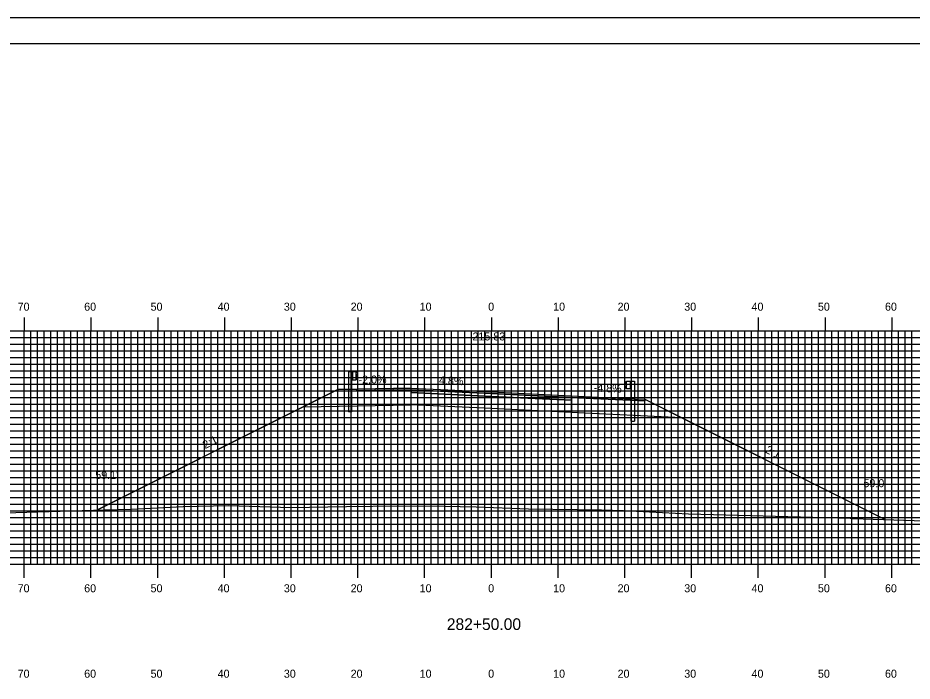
# Model space of a CAD drawing. Extents: x 1811374 to 1811717, y 442591 to 442811.
# Drawn here: x 1811468.4 to 1811602.4, y 442711.2 to 442810.5 of the extents above; entities that cross this region are included whole.
import ezdxf

# ---------------------------------------------------------------- set-up
doc = ezdxf.new("R2010")
doc.units = 0
for name, color, linetype in [('ANNOTATION', 7, 'Continuous'), ('BORDER', 7, 'Continuous'), ('D_Guardrail_Beam_Lt', 7, 'Continuous'), ('D_Guardrail_Beam_Rt', 7, 'Continuous'), ('D_Roadway_Centerline', 7, 'Continuous'), ('D_Roadway_Centerline_Text', 7, 'Continuous'), ('D_Roadway_Edge_Shoulder', 7, 'Continuous'), ('D_Roadway_Edge_TW', 7, 'Continuous'), ('D_Roadway_Pavement', 7, 'Continuous'), ('D_Roadway_SlopeLines', 7, 'Continuous'), ('D_Roadway_SubGrade', 7, 'Continuous'), ('D_Text_Standard', 7, 'Continuous'), ('H_V ANNOTATION', 7, 'Continuous'), ('MAJOR', 7, 'Continuous'), ('MINOR', 7, 'Continuous'), ('PLOT BOUNDARY', 7, 'Continuous'), ('S_Roadway_Centerline', 7, 'Continuous')]:
    doc.layers.add(name, color=color, linetype=linetype)

msp = doc.modelspace()

# ---------------------------------------------------------------- linework, layer by layer
at = {"layer": 'BORDER'}
msp.add_lwpolyline([(1811389.8, 442596.67), (1811709.8, 442596.67), (1811709.8, 442806.67), (1811389.8, 442806.67)], close=True, dxfattribs=at)
at = {"layer": 'D_Guardrail_Beam_Lt'}
for p, q in [((1811517.97, 442757.49), (1811517.97, 442751.49)), ((1811518.44, 442757.49), (1811517.97, 442757.49)), ((1811519.13, 442757.49), (1811518.44, 442757.49)), ((1811518.44, 442757.49), (1811518.44, 442756.33)), ((1811518.51, 442757.49), (1811518.51, 442756.33)), ((1811518.61, 442757.49), (1811518.61, 442756.33)), ((1811519.13, 442756.33), (1811519.13, 442757.49)), ((1811519.13, 442757.41), (1811519.21, 442757.39)), ((1811519.14, 442756.94), (1811519.14, 442756.87)), ((1811519.37, 442757.14), (1811519.17, 442757.01)), ((1811519.22, 442757.39), (1811519.37, 442757.29)), ((1811518.44, 442756.33), (1811519.13, 442756.33)), ((1811518.47, 442751.49), (1811518.47, 442756.33)), ((1811519.21, 442756.42), (1811519.13, 442756.41)), ((1811519.17, 442756.81), (1811519.37, 442756.67)), ((1811519.37, 442756.53), (1811519.22, 442756.43)), ((1811518.47, 442751.49), (1811517.97, 442751.49))]:
    msp.add_line(p, q, dxfattribs=at)
for centre, major_axis, start_param, end_param in [((1811519.22, 442756.94), (-0.0789, 0), 5.323254, 6.283185), ((1811519.22, 442756.87), (-0.0789, 0), 6.283185, 7.243116), ((1811519.2, 442757.35), (0.0417, 0), 0.959931, 1.376053), ((1811519.32, 442757.22), (0.0877, 0), 5.323254, 7.243116), ((1811519.2, 442756.46), (0.0417, 0), 4.907132, 5.323254), ((1811519.32, 442756.6), (0.0877, 0), 5.323254, 7.243116)]:
    msp.add_ellipse(centre, major_axis=major_axis, ratio=0.995501, start_param=start_param, end_param=end_param, dxfattribs=at)
at = {"layer": 'D_Guardrail_Beam_Rt'}
for p, q in [((1811559.58, 442756.01), (1811559.44, 442755.91)), ((1811559.44, 442755.77), (1811559.64, 442755.63)), ((1811559.67, 442756.03), (1811559.6, 442756.02)), ((1811559.67, 442756.12), (1811560.36, 442756.12)), ((1811559.67, 442754.95), (1811559.67, 442756.12)), ((1811559.67, 442755.57), (1811559.67, 442755.5)), ((1811560.19, 442756.12), (1811560.19, 442754.95)), ((1811560.3, 442756.12), (1811560.3, 442754.95)), ((1811560.36, 442756.12), (1811560.83, 442756.12)), ((1811560.36, 442756.12), (1811560.36, 442754.95)), ((1811560.83, 442756.12), (1811560.83, 442750.12)), ((1811559.64, 442755.43), (1811559.44, 442755.3)), ((1811559.44, 442755.15), (1811559.58, 442755.05)), ((1811559.6, 442755.05), (1811559.67, 442755.03)), ((1811560.36, 442754.95), (1811559.67, 442754.95)), ((1811560.34, 442750.12), (1811560.34, 442754.95)), ((1811560.34, 442750.12), (1811560.83, 442750.12))]:
    msp.add_line(p, q, dxfattribs=at)
for centre, major_axis, start_param, end_param in [((1811559.49, 442755.84), (-0.0877, 0), 5.323254, 7.243116), ((1811559.61, 442755.98), (-0.0417, 0), 4.907132, 5.323254), ((1811559.59, 442755.57), (0.0789, 0), 0, 0.959931), ((1811559.59, 442755.5), (0.0789, 0), 5.323254, 6.283185), ((1811559.49, 442755.23), (-0.0877, 0), 5.323254, 7.243116), ((1811559.61, 442755.09), (-0.0417, 0), 0.959931, 1.376053)]:
    msp.add_ellipse(centre, major_axis=major_axis, ratio=0.995501, start_param=start_param, end_param=end_param, dxfattribs=at)
at = {"layer": 'D_Roadway_Centerline'}
msp.add_lwpolyline([(1811480.3, 442736.8), (1811511.19, 442752.24), (1811516.4, 442754.85), (1811519.4, 442754.91), (1811527.4, 442755.07), (1811539.4, 442754.49), (1811551.4, 442753.92), (1811559.4, 442753.53), (1811562.4, 442753.39), (1811567.93, 442750.62), (1811598.42, 442735.38)], dxfattribs=at)
at = {"layer": 'D_Roadway_Edge_Shoulder'}
for points in [[(1811527.4, 442755.07), (1811519.4, 442754.91), (1811519.4, 442754.91), (1811516.4, 442754.85), (1811516.4, 442754.6), (1811527.4, 442754.82)], [(1811551.4, 442753.92), (1811559.4, 442753.53), (1811559.4, 442753.53), (1811562.4, 442753.39), (1811562.4, 442753.14), (1811551.4, 442753.67)]]:
    msp.add_lwpolyline(points, close=True, dxfattribs=at)
at = {"layer": 'D_Roadway_Edge_TW'}
msp.add_lwpolyline([(1811527.4, 442754.82), (1811527.4, 442755.07), (1811539.4, 442754.49), (1811551.4, 442753.92), (1811551.4, 442753.67), (1811539.4, 442754.24)], close=True, dxfattribs=at)
at = {"layer": 'D_Roadway_Pavement'}
msp.add_lwpolyline([(1811527.4, 442754.4), (1811527.4, 442754.82), (1811539.4, 442754.24), (1811551.4, 442753.67), (1811551.4, 442753.25), (1811539.4, 442753.83)], close=True, dxfattribs=at)
for points in [[(1811527.4, 442754.82), (1811527.4, 442754.4)], [(1811551.4, 442753.67), (1811551.4, 442753.25)]]:
    msp.add_lwpolyline(points, dxfattribs=at)
at = {"layer": 'D_Roadway_SlopeLines'}
for points in [[(1811516.4, 442754.85), (1811480.3, 442736.8)], [(1811562.4, 442753.39), (1811598.42, 442735.38)]]:
    msp.add_lwpolyline(points, dxfattribs=at)
at = {"layer": 'D_Roadway_SubGrade'}
for points in [[(1811527.4, 442754.4), (1811527.4, 442754.82), (1811516.4, 442754.6), (1811516.4, 442754.85), (1811511.19, 442752.24), (1811527.4, 442752.57)], [(1811527.4, 442752.57), (1811527.4, 442754.82), (1811527.4, 442754.4), (1811539.4, 442753.83), (1811551.4, 442753.25), (1811551.4, 442753.67), (1811551.4, 442751.42), (1811539.4, 442751.99)], [(1811551.4, 442753.25), (1811551.4, 442753.67), (1811562.4, 442753.14), (1811562.4, 442753.39), (1811567.93, 442750.62), (1811551.4, 442751.42)]]:
    msp.add_lwpolyline(points, close=True, dxfattribs=at)
at = {"layer": 'MAJOR'}
for p, q in [((1811469.4, 442765.67), (1811469.4, 442763.67)), ((1811479.4, 442765.67), (1811479.4, 442763.67)), ((1811489.4, 442765.67), (1811489.4, 442763.67)), ((1811499.4, 442765.67), (1811499.4, 442763.67)), ((1811509.4, 442765.67), (1811509.4, 442763.67)), ((1811519.4, 442765.67), (1811519.4, 442763.67)), ((1811529.4, 442765.67), (1811529.4, 442763.67)), ((1811539.4, 442765.67), (1811539.4, 442763.67)), ((1811549.4, 442765.67), (1811549.4, 442763.67)), ((1811559.4, 442765.67), (1811559.4, 442763.67)), ((1811569.4, 442765.67), (1811569.4, 442763.67)), ((1811579.4, 442765.67), (1811579.4, 442763.67)), ((1811589.4, 442765.67), (1811589.4, 442763.67)), ((1811599.4, 442765.67), (1811599.4, 442763.67)), ((1811399.4, 442763.67), (1811679.4, 442763.67)), ((1811399.4, 442763.67), (1811679.4, 442763.67)), ((1811469.4, 442728.67), (1811469.4, 442763.67)), ((1811479.4, 442728.67), (1811479.4, 442763.67)), ((1811489.4, 442728.67), (1811489.4, 442763.67)), ((1811499.4, 442728.67), (1811499.4, 442763.67)), ((1811509.4, 442728.67), (1811509.4, 442763.67)), ((1811519.4, 442728.67), (1811519.4, 442763.67)), ((1811529.4, 442728.67), (1811529.4, 442763.67)), ((1811539.4, 442728.67), (1811539.4, 442763.67)), ((1811549.4, 442728.67), (1811549.4, 442763.67)), ((1811559.4, 442728.67), (1811559.4, 442763.67)), ((1811569.4, 442728.67), (1811569.4, 442763.67)), ((1811579.4, 442728.67), (1811579.4, 442763.67)), ((1811589.4, 442728.67), (1811589.4, 442763.67)), ((1811599.4, 442728.67), (1811599.4, 442763.67)), ((1811399.4, 442758.67), (1811679.4, 442758.67)), ((1811399.4, 442753.67), (1811679.4, 442753.67)), ((1811399.4, 442748.67), (1811679.4, 442748.67)), ((1811399.4, 442743.67), (1811679.4, 442743.67)), ((1811399.4, 442738.67), (1811679.4, 442738.67)), ((1811399.4, 442733.67), (1811679.4, 442733.67)), ((1811399.4, 442728.67), (1811679.4, 442728.67)), ((1811399.4, 442728.67), (1811679.4, 442728.67)), ((1811469.4, 442726.66), (1811469.4, 442728.67)), ((1811479.4, 442726.66), (1811479.4, 442728.67)), ((1811489.4, 442726.66), (1811489.4, 442728.67)), ((1811499.4, 442726.66), (1811499.4, 442728.67)), ((1811509.4, 442726.66), (1811509.4, 442728.67)), ((1811519.4, 442726.66), (1811519.4, 442728.67)), ((1811529.4, 442726.66), (1811529.4, 442728.67)), ((1811539.4, 442726.66), (1811539.4, 442728.67)), ((1811549.4, 442726.66), (1811549.4, 442728.67)), ((1811559.4, 442726.66), (1811559.4, 442728.67)), ((1811569.4, 442726.66), (1811569.4, 442728.67)), ((1811579.4, 442726.66), (1811579.4, 442728.67)), ((1811589.4, 442726.66), (1811589.4, 442728.67)), ((1811599.4, 442726.66), (1811599.4, 442728.67))]:
    msp.add_line(p, q, dxfattribs=at)
at = {"layer": 'MINOR'}
for p, q in [((1811470.4, 442728.67), (1811470.4, 442763.67)), ((1811471.4, 442728.67), (1811471.4, 442763.67)), ((1811472.4, 442728.67), (1811472.4, 442763.67)), ((1811473.4, 442728.67), (1811473.4, 442763.67)), ((1811474.4, 442728.67), (1811474.4, 442763.67)), ((1811475.4, 442728.67), (1811475.4, 442763.67)), ((1811476.4, 442728.67), (1811476.4, 442763.67)), ((1811477.4, 442728.67), (1811477.4, 442763.67)), ((1811478.4, 442728.67), (1811478.4, 442763.67)), ((1811480.4, 442728.67), (1811480.4, 442763.67)), ((1811481.4, 442728.67), (1811481.4, 442763.67)), ((1811482.4, 442728.67), (1811482.4, 442763.67)), ((1811483.4, 442728.67), (1811483.4, 442763.67)), ((1811484.4, 442728.67), (1811484.4, 442763.67)), ((1811485.4, 442728.67), (1811485.4, 442763.67)), ((1811486.4, 442728.67), (1811486.4, 442763.67)), ((1811487.4, 442728.67), (1811487.4, 442763.67)), ((1811488.4, 442728.67), (1811488.4, 442763.67)), ((1811490.4, 442728.67), (1811490.4, 442763.67)), ((1811491.4, 442728.67), (1811491.4, 442763.67)), ((1811492.4, 442728.67), (1811492.4, 442763.67)), ((1811493.4, 442728.67), (1811493.4, 442763.67)), ((1811494.4, 442728.67), (1811494.4, 442763.67)), ((1811495.4, 442728.67), (1811495.4, 442763.67)), ((1811496.4, 442728.67), (1811496.4, 442763.67)), ((1811497.4, 442728.67), (1811497.4, 442763.67)), ((1811498.4, 442728.67), (1811498.4, 442763.67)), ((1811500.4, 442728.67), (1811500.4, 442763.67)), ((1811501.4, 442728.67), (1811501.4, 442763.67)), ((1811502.4, 442728.67), (1811502.4, 442763.67)), ((1811503.4, 442728.67), (1811503.4, 442763.67)), ((1811504.4, 442728.67), (1811504.4, 442763.67)), ((1811505.4, 442728.67), (1811505.4, 442763.67)), ((1811506.4, 442728.67), (1811506.4, 442763.67)), ((1811507.4, 442728.67), (1811507.4, 442763.67)), ((1811508.4, 442728.67), (1811508.4, 442763.67)), ((1811510.4, 442728.67), (1811510.4, 442763.67)), ((1811511.4, 442728.67), (1811511.4, 442763.67)), ((1811512.4, 442728.67), (1811512.4, 442763.67)), ((1811513.4, 442728.67), (1811513.4, 442763.67)), ((1811514.4, 442728.67), (1811514.4, 442763.67)), ((1811515.4, 442728.67), (1811515.4, 442763.67)), ((1811516.4, 442728.67), (1811516.4, 442763.67)), ((1811517.4, 442728.67), (1811517.4, 442763.67)), ((1811518.4, 442728.67), (1811518.4, 442763.67)), ((1811520.4, 442728.67), (1811520.4, 442763.67)), ((1811521.4, 442728.67), (1811521.4, 442763.67)), ((1811522.4, 442728.67), (1811522.4, 442763.67)), ((1811523.4, 442728.67), (1811523.4, 442763.67)), ((1811524.4, 442728.67), (1811524.4, 442763.67)), ((1811525.4, 442728.67), (1811525.4, 442763.67)), ((1811526.4, 442728.67), (1811526.4, 442763.67)), ((1811527.4, 442728.67), (1811527.4, 442763.67)), ((1811528.4, 442728.67), (1811528.4, 442763.67)), ((1811530.4, 442728.67), (1811530.4, 442763.67)), ((1811531.4, 442728.67), (1811531.4, 442763.67)), ((1811532.4, 442728.67), (1811532.4, 442763.67)), ((1811533.4, 442728.67), (1811533.4, 442763.67)), ((1811534.4, 442728.67), (1811534.4, 442763.67)), ((1811535.4, 442728.67), (1811535.4, 442763.67)), ((1811536.4, 442728.67), (1811536.4, 442763.67)), ((1811537.4, 442728.67), (1811537.4, 442763.67)), ((1811538.4, 442728.67), (1811538.4, 442763.67)), ((1811540.4, 442728.67), (1811540.4, 442763.67)), ((1811541.4, 442728.67), (1811541.4, 442763.67)), ((1811542.4, 442728.67), (1811542.4, 442763.67)), ((1811543.4, 442728.67), (1811543.4, 442763.67)), ((1811544.4, 442728.67), (1811544.4, 442763.67)), ((1811545.4, 442728.67), (1811545.4, 442763.67)), ((1811546.4, 442728.67), (1811546.4, 442763.67)), ((1811547.4, 442728.67), (1811547.4, 442763.67)), ((1811548.4, 442728.67), (1811548.4, 442763.67)), ((1811550.4, 442728.67), (1811550.4, 442763.67)), ((1811551.4, 442728.67), (1811551.4, 442763.67)), ((1811552.4, 442728.67), (1811552.4, 442763.67)), ((1811553.4, 442728.67), (1811553.4, 442763.67)), ((1811554.4, 442728.67), (1811554.4, 442763.67)), ((1811555.4, 442728.67), (1811555.4, 442763.67)), ((1811556.4, 442728.67), (1811556.4, 442763.67)), ((1811557.4, 442728.67), (1811557.4, 442763.67)), ((1811558.4, 442728.67), (1811558.4, 442763.67)), ((1811560.4, 442728.67), (1811560.4, 442763.67)), ((1811561.4, 442728.67), (1811561.4, 442763.67)), ((1811562.4, 442728.67), (1811562.4, 442763.67)), ((1811563.4, 442728.67), (1811563.4, 442763.67)), ((1811564.4, 442728.67), (1811564.4, 442763.67)), ((1811565.4, 442728.67), (1811565.4, 442763.67)), ((1811566.4, 442728.67), (1811566.4, 442763.67)), ((1811567.4, 442728.67), (1811567.4, 442763.67)), ((1811568.4, 442728.67), (1811568.4, 442763.67)), ((1811570.4, 442728.67), (1811570.4, 442763.67)), ((1811571.4, 442728.67), (1811571.4, 442763.67)), ((1811572.4, 442728.67), (1811572.4, 442763.67)), ((1811573.4, 442728.67), (1811573.4, 442763.67)), ((1811574.4, 442728.67), (1811574.4, 442763.67)), ((1811575.4, 442728.67), (1811575.4, 442763.67)), ((1811576.4, 442728.67), (1811576.4, 442763.67)), ((1811577.4, 442728.67), (1811577.4, 442763.67)), ((1811578.4, 442728.67), (1811578.4, 442763.67)), ((1811580.4, 442728.67), (1811580.4, 442763.67)), ((1811581.4, 442728.67), (1811581.4, 442763.67)), ((1811582.4, 442728.67), (1811582.4, 442763.67)), ((1811583.4, 442728.67), (1811583.4, 442763.67)), ((1811584.4, 442728.67), (1811584.4, 442763.67)), ((1811585.4, 442728.67), (1811585.4, 442763.67)), ((1811586.4, 442728.67), (1811586.4, 442763.67)), ((1811587.4, 442728.67), (1811587.4, 442763.67)), ((1811588.4, 442728.67), (1811588.4, 442763.67)), ((1811590.4, 442728.67), (1811590.4, 442763.67)), ((1811591.4, 442728.67), (1811591.4, 442763.67)), ((1811592.4, 442728.67), (1811592.4, 442763.67)), ((1811593.4, 442728.67), (1811593.4, 442763.67)), ((1811594.4, 442728.67), (1811594.4, 442763.67)), ((1811595.4, 442728.67), (1811595.4, 442763.67)), ((1811596.4, 442728.67), (1811596.4, 442763.67)), ((1811597.4, 442728.67), (1811597.4, 442763.67)), ((1811598.4, 442728.67), (1811598.4, 442763.67)), ((1811600.4, 442728.67), (1811600.4, 442763.67)), ((1811601.4, 442728.67), (1811601.4, 442763.67)), ((1811602.4, 442728.67), (1811602.4, 442763.67)), ((1811399.4, 442762.67), (1811679.4, 442762.67)), ((1811399.4, 442761.67), (1811679.4, 442761.67)), ((1811399.4, 442760.67), (1811679.4, 442760.67)), ((1811399.4, 442759.67), (1811679.4, 442759.67)), ((1811399.4, 442757.67), (1811679.4, 442757.67)), ((1811399.4, 442756.67), (1811679.4, 442756.67)), ((1811399.4, 442755.67), (1811679.4, 442755.67)), ((1811399.4, 442754.67), (1811679.4, 442754.67)), ((1811399.4, 442752.67), (1811679.4, 442752.67)), ((1811399.4, 442751.67), (1811679.4, 442751.67)), ((1811399.4, 442750.67), (1811679.4, 442750.67)), ((1811399.4, 442749.67), (1811679.4, 442749.67)), ((1811399.4, 442747.67), (1811679.4, 442747.67)), ((1811399.4, 442746.67), (1811679.4, 442746.67)), ((1811399.4, 442745.67), (1811679.4, 442745.67)), ((1811399.4, 442744.67), (1811679.4, 442744.67)), ((1811399.4, 442742.67), (1811679.4, 442742.67)), ((1811399.4, 442741.67), (1811679.4, 442741.67)), ((1811399.4, 442740.67), (1811679.4, 442740.67)), ((1811399.4, 442739.67), (1811679.4, 442739.67)), ((1811399.4, 442737.67), (1811679.4, 442737.67)), ((1811399.4, 442736.67), (1811679.4, 442736.67)), ((1811399.4, 442735.67), (1811679.4, 442735.67)), ((1811399.4, 442734.67), (1811679.4, 442734.67)), ((1811399.4, 442732.67), (1811679.4, 442732.67)), ((1811399.4, 442731.67), (1811679.4, 442731.67)), ((1811399.4, 442730.67), (1811679.4, 442730.67)), ((1811399.4, 442729.67), (1811679.4, 442729.67))]:
    msp.add_line(p, q, dxfattribs=at)
at = {"layer": 'PLOT BOUNDARY'}
msp.add_lwpolyline([(1811373.62, 442590.55), (1811713.62, 442590.55), (1811713.62, 442810.55), (1811373.62, 442810.55)], close=True, dxfattribs=at)
at = {"layer": 'S_Roadway_Centerline'}
msp.add_lwpolyline([(1811463.07, 442736.3), (1811481.41, 442736.83), (1811485.37, 442736.94), (1811493.22, 442737.31), (1811500.05, 442737.47), (1811509.34, 442737.17), (1811517.68, 442737.35), (1811525.52, 442737.44), (1811532.32, 442737.4), (1811537.11, 442737.3), (1811544.97, 442736.98), (1811555.91, 442736.83), (1811559.18, 442736.71), (1811568.94, 442736.25), (1811593.14, 442735.56), (1811593.38, 442735.55), (1811593.54, 442735.54), (1811613.48, 442734.89)], dxfattribs=at)

# ---------------------------------------------------------------- texts
at = {"layer": 'ANNOTATION'}
for s, rotation, p in [('-2.0%', 1.1458, (1811519.51, 442755.71)), ('4.8%', 357.2519, (1811531.53, 442755.67)), ('-4.8%', 357.2519, (1811554.71, 442754.56)), ('2:1', 26.5651, (1811496.5, 442745.93)), ('2:1', 333.4349, (1811580.35, 442745.45))]:
    msp.add_text(s, height=1.2, rotation=rotation, dxfattribs=at).set_placement(p)
at = {"layer": 'D_Roadway_Centerline'}
for s in ['C', 'L']:
    msp.add_text(s, height=0.0146, dxfattribs=at).set_placement((1811539.4, 442754.49))
at = {"layer": 'D_Roadway_Centerline_Text'}
msp.add_text('215.83', height=1.2, dxfattribs=at).set_placement((1811536.57, 442762.21))
at = {"layer": 'D_Text_Standard'}
for s, p in [("59.1'", (1811480.04, 442741.45)), ("59.0'", (1811595.15, 442740.22))]:
    msp.add_text(s, height=1.2, dxfattribs=at).set_placement(p)
at = {"layer": 'H_V ANNOTATION'}
for s, height, p in [('70', 1.2, (1811468.41, 442766.67)), ('60', 1.2, (1811478.38, 442766.67)), ('50', 1.2, (1811488.33, 442766.67)), ('40', 1.2, (1811498.38, 442766.67)), ('30', 1.2, (1811508.3, 442766.67)), ('20', 1.2, (1811518.31, 442766.67)), ('10', 1.2, (1811528.65, 442766.67)), ('0', 1.2, (1811538.92, 442766.67)), ('10', 1.2, (1811548.65, 442766.67)), ('20', 1.2, (1811558.31, 442766.67)), ('30', 1.2, (1811568.3, 442766.67)), ('40', 1.2, (1811578.38, 442766.67)), ('50', 1.2, (1811588.33, 442766.67)), ('60', 1.2, (1811598.38, 442766.67)), ('70', 1.2, (1811468.41, 442724.47)), ('60', 1.2, (1811478.38, 442724.47)), ('50', 1.2, (1811488.33, 442724.47)), ('40', 1.2, (1811498.38, 442724.47)), ('30', 1.2, (1811508.3, 442724.47)), ('20', 1.2, (1811518.31, 442724.47)), ('10', 1.2, (1811528.65, 442724.47)), ('0', 1.2, (1811538.92, 442724.47)), ('10', 1.2, (1811548.65, 442724.47)), ('20', 1.2, (1811558.31, 442724.47)), ('30', 1.2, (1811568.3, 442724.47)), ('40', 1.2, (1811578.38, 442724.47)), ('50', 1.2, (1811588.33, 442724.47)), ('60', 1.2, (1811598.38, 442724.47)), ('282+50.00', 1.75, (1811532.72, 442718.82)), ('70', 1.2, (1811468.41, 442711.67)), ('60', 1.2, (1811478.38, 442711.67)), ('50', 1.2, (1811488.33, 442711.67)), ('40', 1.2, (1811498.38, 442711.67)), ('30', 1.2, (1811508.3, 442711.67)), ('20', 1.2, (1811518.31, 442711.67)), ('10', 1.2, (1811528.65, 442711.67)), ('0', 1.2, (1811538.92, 442711.67)), ('10', 1.2, (1811548.65, 442711.67)), ('20', 1.2, (1811558.31, 442711.67)), ('30', 1.2, (1811568.3, 442711.67)), ('40', 1.2, (1811578.38, 442711.67)), ('50', 1.2, (1811588.33, 442711.67)), ('60', 1.2, (1811598.38, 442711.67))]:
    msp.add_text(s, height=height, dxfattribs=at).set_placement(p)

doc.saveas('drawing.dxf')
